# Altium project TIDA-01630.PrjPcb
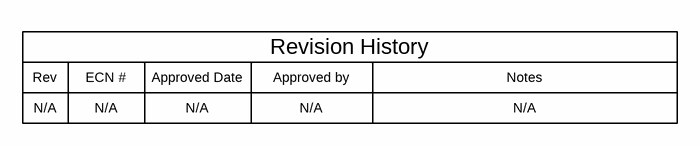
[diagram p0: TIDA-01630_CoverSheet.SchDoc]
TID: 01630; TechSupport: http://www.ti.com/support; SCH_Rev: E2; PRJ_Title: High EMC Immunity RS485 Interface  Reference Design for Tamagawa Encoders; PRJ_Number: TIDA-01630; PRJ_Engineer: Kristen Mogensen; PRJ_Customer: Internal Use Only; PCB_Rev: E2; PCB_Layout: Zoe Boele; CopyrightYear: 2017
5 sheets, 119 parts. Net scope: global (net labels, ports and power ports of the same name join across sheets).
Board file: TIDA-01630_PCB.PcbDoc
Sheets:
  TIDA-01630_CoverSheet.SchDoc
  TIDA-01630_EVM_Hardware.SchDoc
  TIDA-01630_Interface.SchDoc
  TIDA-01630_PowerSupply.SchDoc
  TIDA-01630_Transceivers.SchDoc

## Sheet TIDA-01630_CoverSheet.SchDoc
size 431 x 279 mm; Date: Not shown in title block; ApprovedBy: Not shown in title block; CheckedBy: Not shown in title block; Author: Not shown in title block; CompanyName: Not shown in title block; Engineer: Not shown in title block; Organization: Not shown in title block; Address1: Not shown in title block; Address2: Not shown in title block; Address3: Not shown in title block; Address4: Not shown in title block; DocumentNumber: 1; Revision: Use project parameter SCH_Rev; SheetNumber: 1; SheetTotal: 3; PageSetup: Record=PageOptions¦CenterHorizontal=True¦CenterVertical=True¦PrintScale=1.00¦XCorrection=1.00¦YCorrection=1.00¦PrintKind=0¦BorderSize=5000000¦LeftOffset=0¦BottomOffset=0¦Orientation=2¦PaperLength=1000¦PaperWidth=1000¦Scale=100¦PaperSource=15¦PrintQuality=600¦MediaType=1¦DitherType=10¦PaperKind=Letter¦PrintScaleMode=1

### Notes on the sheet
- Rev
- N/A
- ECN #
- Approved Date
- Approved by
- Revision History
- Notes

## Sheet TIDA-01630_EVM_Hardware.SchDoc
size 431 x 279 mm; Date: Not shown in title block; ApprovedBy: Not shown in title block; CheckedBy: Not shown in title block; Author: Not shown in title block; CompanyName: Not shown in title block; Engineer: Not shown in title block; Organization: Not shown in title block; Address1: Not shown in title block; Address2: Not shown in title block; Address3: Not shown in title block; Address4: Not shown in title block; DocumentNumber: 1; Revision: Use project parameter SCH_Rev; SheetNumber: 3; SheetTotal: 3; PageSetup: Record=PageOptions¦CenterHorizontal=True¦CenterVertical=True¦PrintScale=1.00¦XCorrection=1.00¦YCorrection=1.00¦PrintKind=0¦BorderSize=5000000¦LeftOffset=0¦BottomOffset=0¦Orientation=2¦PaperLength=1000¦PaperWidth=1000¦Scale=100¦PaperSource=15¦PrintQuality=600¦MediaType=1¦DitherType=10¦PaperKind=Letter¦PrintScaleMode=1
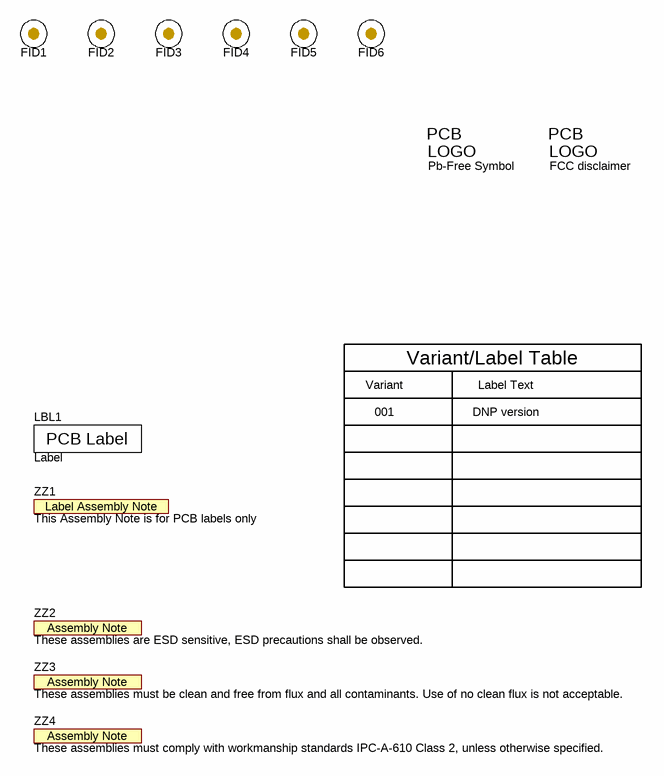
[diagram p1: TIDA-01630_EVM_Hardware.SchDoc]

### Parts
FID1  Fiducial  [Fiducial10-20]  (value not drawn)
FID2  Fiducial  [Fiducial10-20]  (value not drawn)
FID3  Fiducial  [Fiducial10-20]  (value not drawn)
FID4  Fiducial  [Fiducial10-20]  (value not drawn)
FID5  Fiducial  [Fiducial10-20]  (value not drawn)
FID6  Fiducial  [Fiducial10-20]  (value not drawn)
LBL1  Label  [Label_650x200]
Logo2  Pb-Free Symbol  [Pb-Free_Overlay_Small]  (no BOM)
Logo3  FCC disclaimer  [FCC_disclaimer]  (no BOM)
ZZ1  This Assembly Note is for PCB labels only  [AssemblyNoteLabel]  (no BOM)
ZZ2  These assemblies are ESD sensitive, ESD precautions shall be observed.  [AssemblyNote]  (no BOM)
ZZ3  These assemblies must be clean and free from flux and all contaminants. Use of no clean flux is not acceptable.  [AssemblyNote]  (no BOM)
ZZ4  These assemblies must comply with workmanship standards IPC-A-610 Class 2, unless otherwise specified.  [AssemblyNote]  (no BOM)

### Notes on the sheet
- Variant
- Variant/Label Table
- Label Text
- 001
- DNP version

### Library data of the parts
FID1-FID6 = CMP-0077181-1: Fiducial mark.  There is nothing to buy or mount.
LBL1 = CMP-0003625-1: Thermal Transfer Printable Labels, 0.650" W x 0.200" H - 10,000 per roll; Manufacturer: Brady; PartNumber: THT-14-423-10; Note: Size: 0.65" x 0.20 "
Logo2 = CMP-0074839-1: SymbolCreator: a0412235
Logo3 = CMP-0074847-1: FCC_disclaimer
ZZ1 = CMP-0003616-3
ZZ2 = CMP-0077236-1
ZZ3 = CMP-0077237-1
ZZ4 = CMP-0077238-1

## Sheet TIDA-01630_Interface.SchDoc
size 431 x 279 mm; Date: Not shown in title block; ApprovedBy: Not shown in title block; CheckedBy: Not shown in title block; Author: Not shown in title block; CompanyName: Not shown in title block; Engineer: Not shown in title block; Organization: Not shown in title block; Address1: Not shown in title block; Address2: Not shown in title block; Address3: Not shown in title block; Address4: Not shown in title block; DocumentNumber: 1; Revision: Use project parameter SCH_Rev; SheetNumber: 2; SheetTotal: 3; PageSetup: Record=PageOptions¦CenterHorizontal=True¦CenterVertical=True¦PrintScale=0.64¦XCorrection=1.00¦YCorrection=1.00¦PrintKind=0¦BorderSize=5000000¦LeftOffset=0¦BottomOffset=0¦Orientation=2¦PaperLength=1000¦PaperWidth=1000¦Scale=100¦PaperSource=15¦PrintQuality=600¦MediaType=1¦DitherType=10¦PrintScaleMode=1¦PaperKind=8 1/2x11¦PaperIndex=1
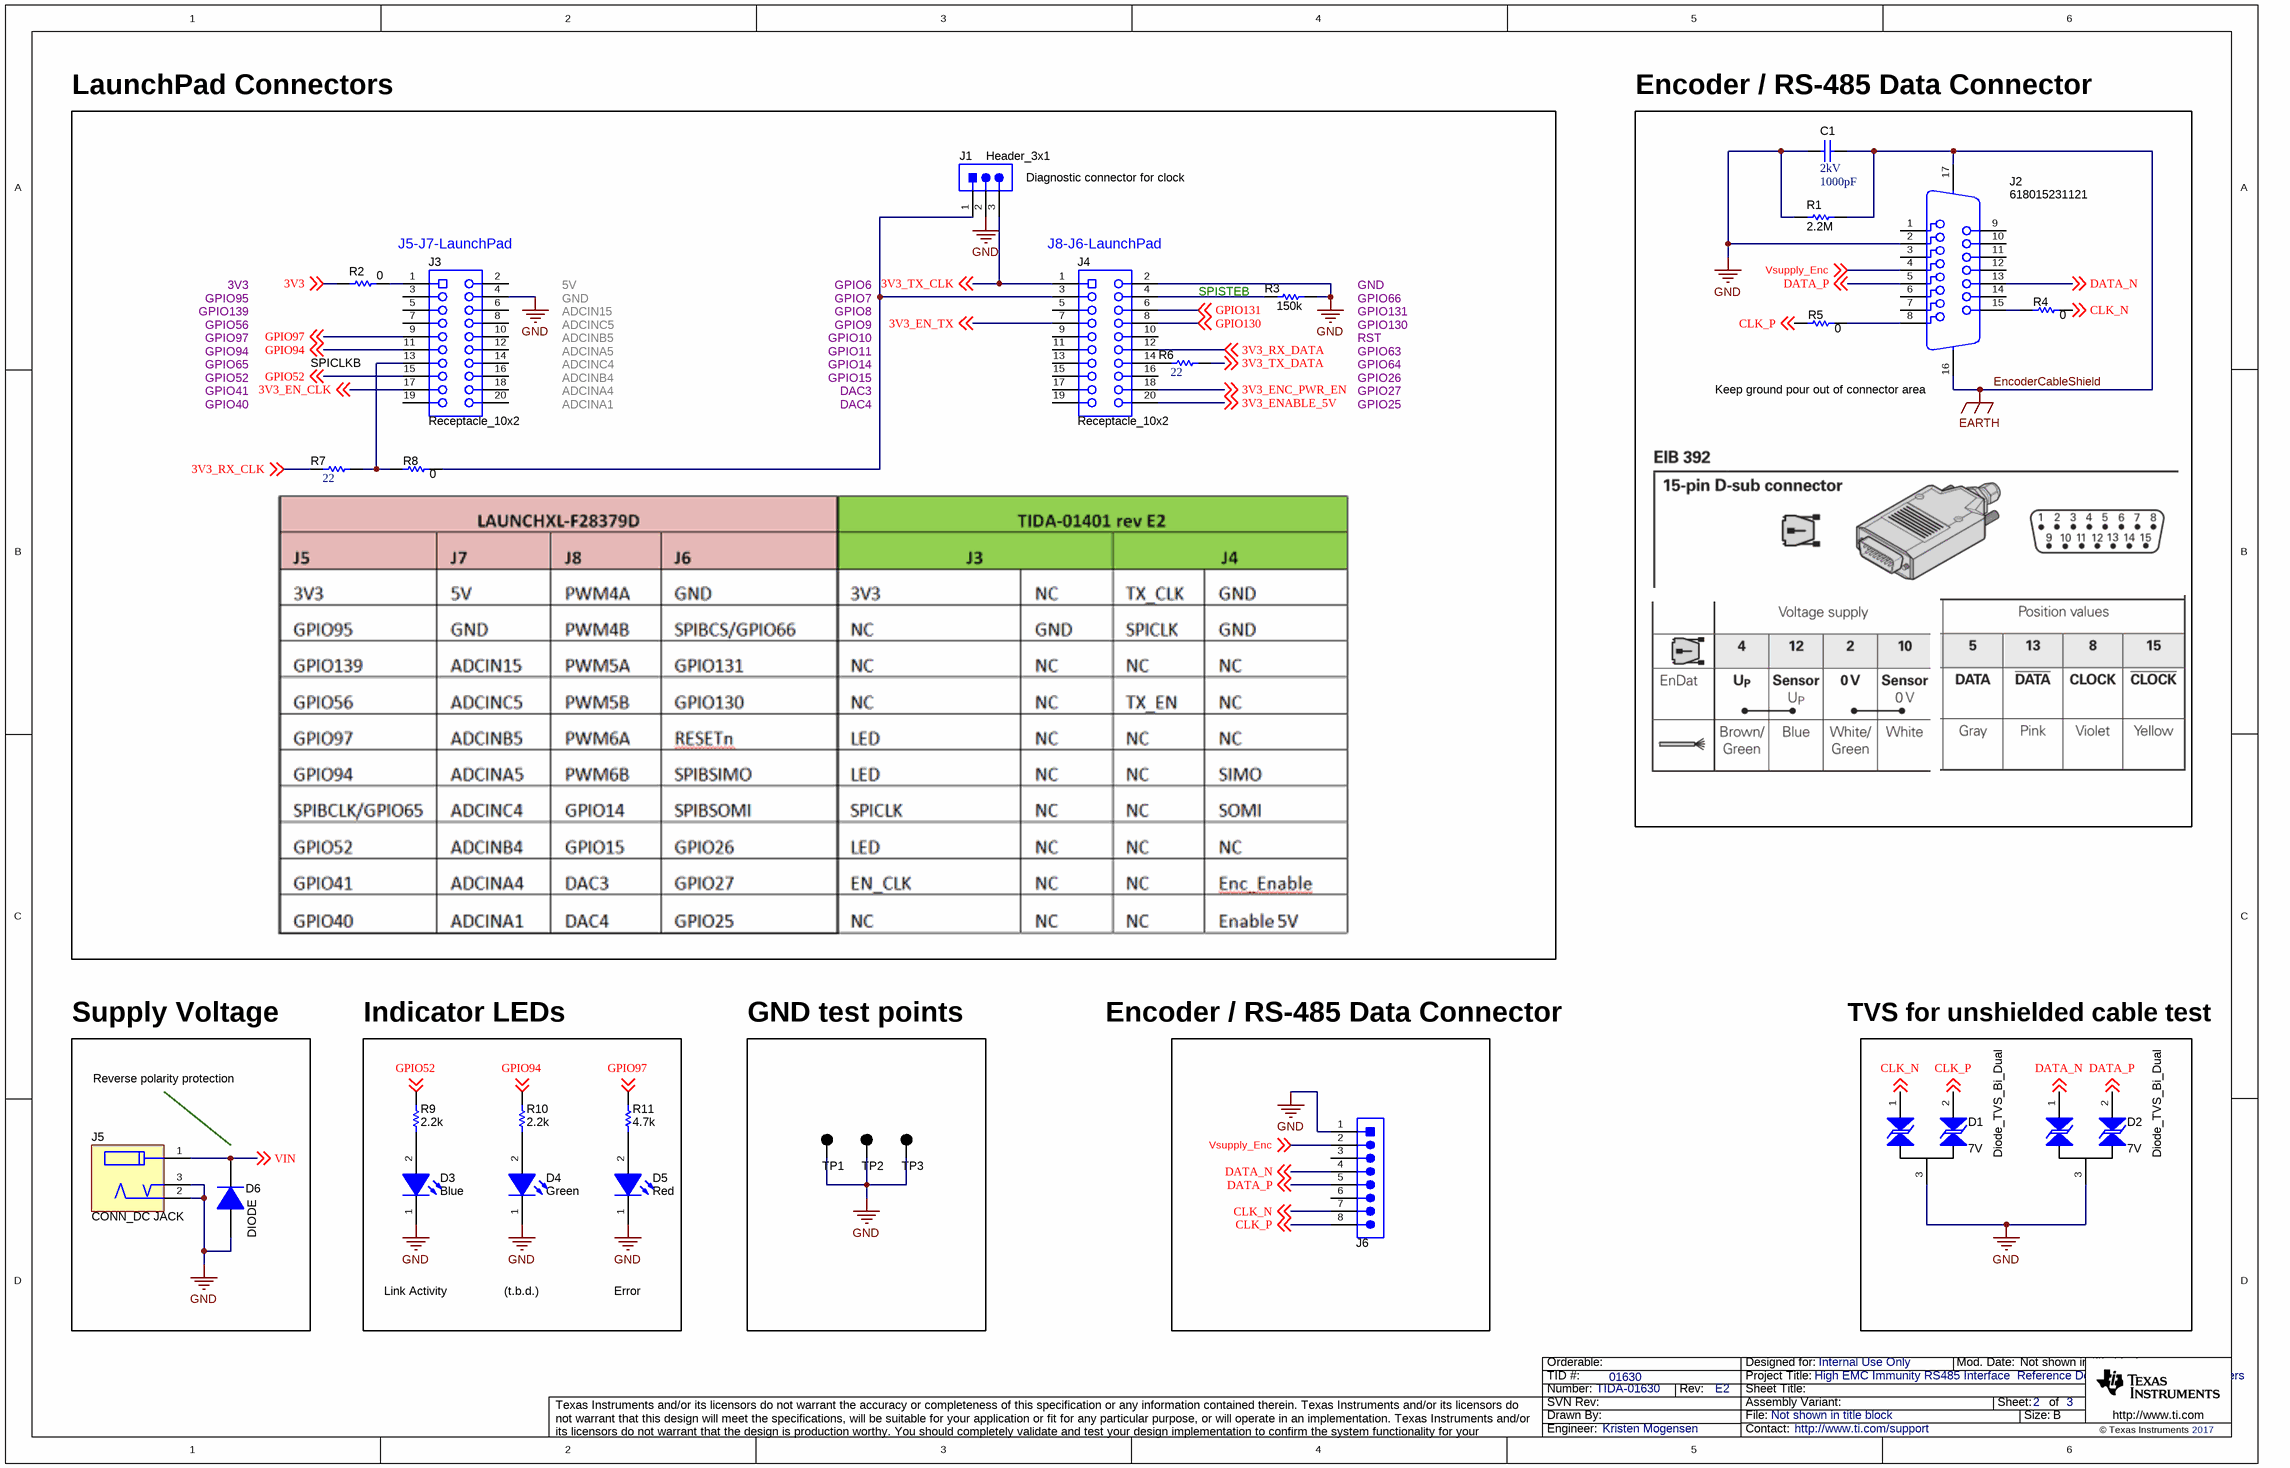
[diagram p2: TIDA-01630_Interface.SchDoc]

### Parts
C1  VDC_V: 2kV  ValueDisplayed: 1000pF  [1812_220]  (hidden comment: 1812GC102KAT1A)
D1  Diode_TVS_Bi_Dual  value 7V  [SOT-23]
D2  Diode_TVS_Bi_Dual  value 7V  [SOT-23]
D3  value Blue  [WL-SMCW_Blue]  (hidden comment: LED_A2_K1)
D4  value Green  [WL-SMCW_GREEN]  (hidden comment: LED_A2_K1)
D5  value Red  [WL-SMCW_RED]  (hidden comment: LED_A2_K1)
D6  DIODE  [PowerDI123]
J1  Header_3x1  [FCI_68001-403HLF]
J2  618015231121  [Wurth_618015231121]
J3  Receptacle_10x2  [CONN_SSW-110-23-F-D]
J4  Receptacle_10x2  [CONN_SSW-110-23-F-D]
J5  CONN_DC JACK  [Switchcraft_RASM722]
J6  Header_8x1  [SULLINS_PEC08SAAN]  (value not drawn)
R1  ValueDisplayed: 2.2M  [1206]  (hidden comment: Resistor)
R2  ValueDisplayed: 0  [0603]  (hidden comment: Resistor)
R3  ValueDisplayed: 150k  [0402S]  (hidden comment: Resistor)
R4  ValueDisplayed: 0  [0402S]  (hidden comment: Resistor)
R5  ValueDisplayed: 0  [0402S]  (hidden comment: Resistor)
R6  ValueDisplayed: 22  [0402S]  (hidden comment: CRCW040222R0JNED)
R7  ValueDisplayed: 22  [0402S]  (hidden comment: CRCW040222R0JNED)
R8  ValueDisplayed: 0  [0402S]  (hidden comment: Resistor)
R9  ValueDisplayed: 2.2k  [0402S]  (hidden comment: Resistor)
R10  ValueDisplayed: 2.2k  [0402S]  (hidden comment: Resistor)
R11  ValueDisplayed: 4.7k  [0402S]  (hidden comment: Resistor)
TP1  5001  [Keystone5001]  (value not drawn)
TP2  5001  [Keystone5001]  (value not drawn)
TP3  5001  [Keystone5001]  (value not drawn)

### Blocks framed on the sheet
Keep ground pour out of connector area: C1 J2 R1 R4 R5
Reverse polarity protection: D6 J5

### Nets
EncoderCableShield: C1.1 J2.16(MH1) J2.17(MH2) R1.2  [also labelled EARTH]
GND: C1.2 D1.3 D2.3 D3.1(K) D4.1(K) D5.1(K) D6.2(A) J1.2 J2.2 J3.4 J4.2 J5.2 J5.3 J6.1 R1.1 R3.2 TP1.1 TP2.1 TP3.1
3V3: R2.1 ; off-sheet 3V3
3V3_EN_CLK: J3.17 ; off-sheet 3V3_EN_CLK
3V3_EN_TX: J4.7 ; off-sheet 3V3_EN_TX
3V3_ENABLE_5V: J4.20 ; off-sheet 3V3_ENABLE_5V
3V3_ENC_PWR_EN: J4.18 ; off-sheet 3V3_ENC_PWR_EN
3V3_RX_CLK: R7.1 ; off-sheet 3V3_RX_CLK
3V3_RX_DATA: J4.12 ; off-sheet 3V3_RX_DATA
3V3_TX_CLK: J1.3 J4.1 ; off-sheet 3V3_TX_CLK
3V3_TX_DATA: R6.2 ; off-sheet 3V3_TX_DATA
CLK_N: D1.1 J6.7 R4.2 ; off-sheet CLK_N
CLK_P: D1.2 J6.8 R5.1 ; off-sheet CLK_P
DATA_N: D2.1 J2.13 J6.4 ; off-sheet DATA_N
DATA_P: D2.2 J2.5 J6.5 ; off-sheet DATA_P
GPIO52: J3.15 R9.2 ; off-sheet GPIO52
GPIO94: J3.11 R10.2 ; off-sheet GPIO94
GPIO97: J3.9 R11.2 ; off-sheet GPIO97
GPIO130: J4.8 ; off-sheet GPIO130
GPIO131: J4.6 ; off-sheet GPIO131
VIN: D6.1(K) J5.1 ; off-sheet VIN
Vsupply_Enc: J2.4 J6.2 ; off-sheet Vsupply_Enc
NetD3_2: D3.2(A) R9.1
NetD4_2: D4.2(A) R10.1
NetD5_2: D5.2(A) R11.1
NetJ1_1: J1.1 J4.3 R8.2
NetJ2_8: J2.8 R5.2
NetJ2_15: J2.15 R4.1
NetJ3_1: J3.1 R2.2
NetJ3_13: J3.13 R7.2 R8.1
NetJ4_4: J4.4 R3.1
NetJ4_14: J4.14 R6.1

Not connected (* = marked no-connect by the designer): J2 1 3 6 7 9 10 11 12 14; J3 2 3 5 6 7 8 10 12 14 16 18 19 20; J4 5 9 10 11 13 15 16 17 19; J6 3 6

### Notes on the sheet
- LaunchPad Connectors
- (near C1) Encoder / RS-485 Data Connector
- (near J1) Diagnostic connector for clock
- J5-J7-LaunchPad
- (near J4) J8-J6-LaunchPad
- (near R3) SPISTEB
- SPICLKB
- 3V3
  GPIO95
  GPIO139
  GPIO56
  GPIO97
  GPIO94
  GPIO65
  GPIO52
  GPIO41
  GPIO40
- 5V
  GND
  ADCIN15
  ADCINC5
  ADCINB5
  ADCINA5
  ADCINC4
  ADCINB4
  ADCINA4
  ADCINA1
- GPIO6
  GPIO7
  GPIO8
  GPIO9
  GPIO10
  GPIO11
  GPIO14
  GPIO15
  DAC3
  DAC4
- GND
  GPIO66
  GPIO131
  GPIO130
  RST
  GPIO63
  GPIO64
  GPIO26
  GPIO27
  GPIO25
- Supply Voltage
- Indicator LEDs
- GND test points
- Encoder / RS-485 Data Connector
- TVS for unshielded cable test
- Link Activity
- (t.b.d.)
- Error

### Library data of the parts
C1 = CMP-0064918-2: CAP, CERM, 1000 pF, 2000 V,+/- 10%, X7R, 1812; Manufacturer: AVX; TaMin_C: -55°C; Polarized: N; SizeAreaWB_mm2: 23.1; Value1: Unknown; U/M: EA; Value: 1000pF; TaMax_C: 125°C; SizeZ_mm: 2.2; SizeX_mm: 4.5; SizeY_mm: 3.2; Cap_Case: 1812; Value2: 2000V; SizeArea_mm2: 14.4; CompType: Capacitor; Cap_F: 1nF; AEC Category: Q200
D1 D2 = CMP-0005928-1: Diode, TVS, Bi, 7 V, SOT-23; PartNumber: CDSOT23-SM712; Manufacturer: Bourns; U/M: EA; Value1: W; SizeAreaWB_mm2: 14; SizeArea_mm2: 7.5; SizeX_mm: 2.5; SizeY_mm: 3; SizeZ_mm: 1.1; AEC Category: Q101
D3 = CMP-0002946-2: LED, Blue, SMD; Manufacturer: Wurth Elektronik; PartNumber: 150060BS75000; Type: InGaN; Vf_V: 3.2V; Io_A: 30mA; Vr_V: 5V; Tjmax_C: 85°C; Power_TotalModule: 105mW; Value1: 0.105W; Angle: 140; U/M: EA
D4 = CMP-0002905-1: LED, Green, SMD; Manufacturer: Wurth Elektronik; PartNumber: 150060GS75000; Type: InGaN; Vf_V: 3.2V; Io_A: 20mA; Tjmax_C: 85°C; Value1: W; Angle: 140; U/M: EA
D5 = CMP-0002947-2: LED, Red, SMD; Manufacturer: Wurth Elektronik; PartNumber: 150060RS75000; Type: AlInGaP; Vf_V: 2V; Io_A: 30mA; Vr_V: 5V; Tjmax_C: 85°C; Power_TotalModule: 72mW; Value1: 0.072W; Angle: 140; U/M: EA
D6 = CMP-0029284-1: Diode, Super Barrier Rectifier, 40 V, 3 A, AEC-Q101, PowerDI123; PartNumber: SBRT3U40P1-7; Manufacturer: Diodes Inc.; U/M: EA; Vf_V: 4.9dV; Value: 40V; Value1: 3A; Value2: 0.49V; TJmax_C: 150°C; RJC_CperW: 19; SizeAreaWB_mm2: 13.066; SizeArea_mm2: 6.586; SizeX_mm: 3.7; SizeY_mm: 1.78; SizeZ_mm: 0.98; AEC Category: Q101; AEC Qualified: Y; Green_Lifecycle: Not Set; Green_REACh: Incomplete
J1 = CMP-0065026-1: Header, 2.54mm, 3x1, Tin, TH; PartNumber: 68001-403HLF; Manufacturer: FCI; Pitch_mm: 2.54; Gender: Male; Shrouded: N; Row_Count: 1; Current_A: 3A; Voltage_V: 1.5kV; Cert_CSA: Y; CNHeader: True; CT: False
J2 = CMP-0077259-1: Receptacle, D-Sub, 15 Position, R/A, TH; Manufacturer: Wurth Elektronik; Pitch_mm: 2.77; Gender: Female; Cert_UL: Y; Current_A: 3A; Voltage_V: 125V; ContactFinish: Gold; RowSpacing_mm: 2.84; Row_Count: 2
J3 J4 = CMP-0075442-1: Connector, Receptacle, 100mil, 10x2, Gold plated, TH; PartNumber: SSW-110-23-F-D; Manufacturer: Samtec; CompType: Socket Strip; CNHeader: False; CT: True; Green_Lifecycle: Active; Green_REACh: Passed
J5 = CMP-0075046-1: Power Jack, 2mm, R/A, SMD; PartNumber: RASM722X; Manufacturer: Switchcraft; CNHeader: False
J6 = CMP-0054563-1: Header, 100mil, 8x1, Tin, TH; PartNumber: PEC08SAAN; Manufacturer: Sullins Connector Solutions; Pitch_mm: 2.54; Gender: Male; Shrouded: N; Row_Count: 1; Current_A: 3A; Voltage_V: 1.8kV; Cert_UL: Y; CNHeader: TRUE; CT: FALSE; Green_Lifecycle: Not Set; Green_REACh: Incomplete
R1 = CMP-0018645-2: RES, 2.2 M, 5%, 0.25 W, 1206; PartNumber: CRCW12062M20JNEA; Manufacturer: Vishay-Dale; Value: 2.2Meg; Value_Code: 2M20; Power_W: 250mW; Value2: 0.25W; VDC_V: 200V; TempCo: 200 ppm/C; SizeArea_mm2: 5.12; SizeX_mm: 3.2; SizeY_mm: 1.6; SizeZ_mm: 1.35; EIA_Code: E24; U/M: EA; AEC Category: Q200
R2 = CMP-0025697-4: RES, 0, 5%, 0.1 W, AEC-Q200 Grade 0, 0603; PartNumber: CRCW06030000Z0EA; Manufacturer: Vishay-Dale; Value: 0; Value_Code: 0000; Power_W: 100mW; Value2: 0.1W; VDC_V: 75V; TempCo: 200 ppm/C; SizeArea_mm2: 1.28; SizeX_mm: 1.6; SizeY_mm: 0.8; SizeZ_mm: 1; EIA_Code: E24; AEC Category: Q200; AEC Qualified: Y
R3 = CMP-0026840-2: RES, 150 k, 5%, 0.063 W, AEC-Q200 Grade 0, 0402; PartNumber: CRCW0402150KJNED; Manufacturer: Vishay-Dale; Value: 150k; Power_W: 63mW; Value2: 0.063W; VDC_V: 50V; TempCo: 200 ppm/C; SizeArea_mm2: 0.5; SizeX_mm: 1; SizeZ_mm: 0.6; EIA_Code: E24; AEC Category: Q200; AEC Qualified: Y; AEC Grade: 0
R4 R5 R8 = CMP-0026822-3: RES, 0, 5%, 0.063 W, AEC-Q200 Grade 0, 0402; PartNumber: CRCW04020000Z0ED; Manufacturer: Vishay-Dale; Value: 0; Value_Code: 0000; Power_W: 63mW; Value2: 0.063W; VDC_V: 50V; TempCo: 200 ppm/C; SizeArea_mm2: 0.5; SizeX_mm: 1; SizeZ_mm: 0.6; EIA_Code: E24; AEC Category: Q200; AEC Qualified: Y
R6 R7 = CMP-0026880-2: RES, 22, 5%, 0.063 W, 0402; Manufacturer: Vishay-Dale; Power_W: 63mW; TempCo: 200 ppm/C; Value_Code: 22R0; U/M: EA; Value: 22; EIA_Code: E24; SizeX_mm: 1; SizeY_mm: 0.5; SizeZ_mm: 0.6; Value2: 0.063W; CompType: Resistor; VDC_V: 50V; AEC Category: Q200
R9 R10 = CMP-0026890-5: RES, 2.2 k, 5%, 0.063 W, AEC-Q200 Grade 0, 0402; PartNumber: CRCW04022K20JNED; Manufacturer: Vishay-Dale; Value: 2.2k; Value_Code: 2k20; Power_W: 63mW; Value2: 0.063W; VDC_V: 50V; TempCo: 200 ppm/C; SizeArea_mm2: 0.5; SizeX_mm: 1; SizeZ_mm: 0.6; EIA_Code: E24; AEC Category: Q200; AEC Qualified: Y; AEC Grade: 0
R11 = CMP-0026938-5: RES, 4.7 k, 5%, 0.063 W, AEC-Q200 Grade 0, 0402; PartNumber: CRCW04024K70JNED; Manufacturer: Vishay-Dale; Value: 4.7k; Value_Code: 4k70; Power_W: 63mW; Value2: 0.063W; VDC_V: 50V; TempCo: 200 ppm/C; SizeArea_mm2: 0.5; SizeX_mm: 1; SizeZ_mm: 0.6; EIA_Code: E24; AEC Category: Q200; AEC Qualified: Y; AEC Grade: 0
TP1-TP3 = CMP-0055138-1: Test Point, Miniature, Black, TH; Manufacturer: Keystone; ContactFinish: Silver; CNHeader: FALSE; CT: TRUE; Green_Lifecycle: Active; Green_REACh: Passed

## Sheet TIDA-01630_PowerSupply.SchDoc
size 431 x 279 mm; Date: Not shown in title block; ApprovedBy: Not shown in title block; CheckedBy: Not shown in title block; Author: Not shown in title block; CompanyName: Not shown in title block; Engineer: Not shown in title block; Organization: Not shown in title block; Address1: Not shown in title block; Address2: Not shown in title block; Address3: Not shown in title block; Address4: Not shown in title block; DocumentNumber: 1; Revision: Use project parameter SCH_Rev; SheetNumber: 2; SheetTotal: 3; PageSetup: Record=PageOptions¦CenterHorizontal=True¦CenterVertical=True¦PrintScale=1.00¦XCorrection=1.00¦YCorrection=1.00¦PrintKind=0¦BorderSize=5000000¦LeftOffset=0¦BottomOffset=0¦Orientation=2¦PaperLength=1000¦PaperWidth=1000¦Scale=100¦PaperSource=15¦PrintQuality=600¦MediaType=1¦DitherType=10¦PaperKind=Letter¦PrintScaleMode=1
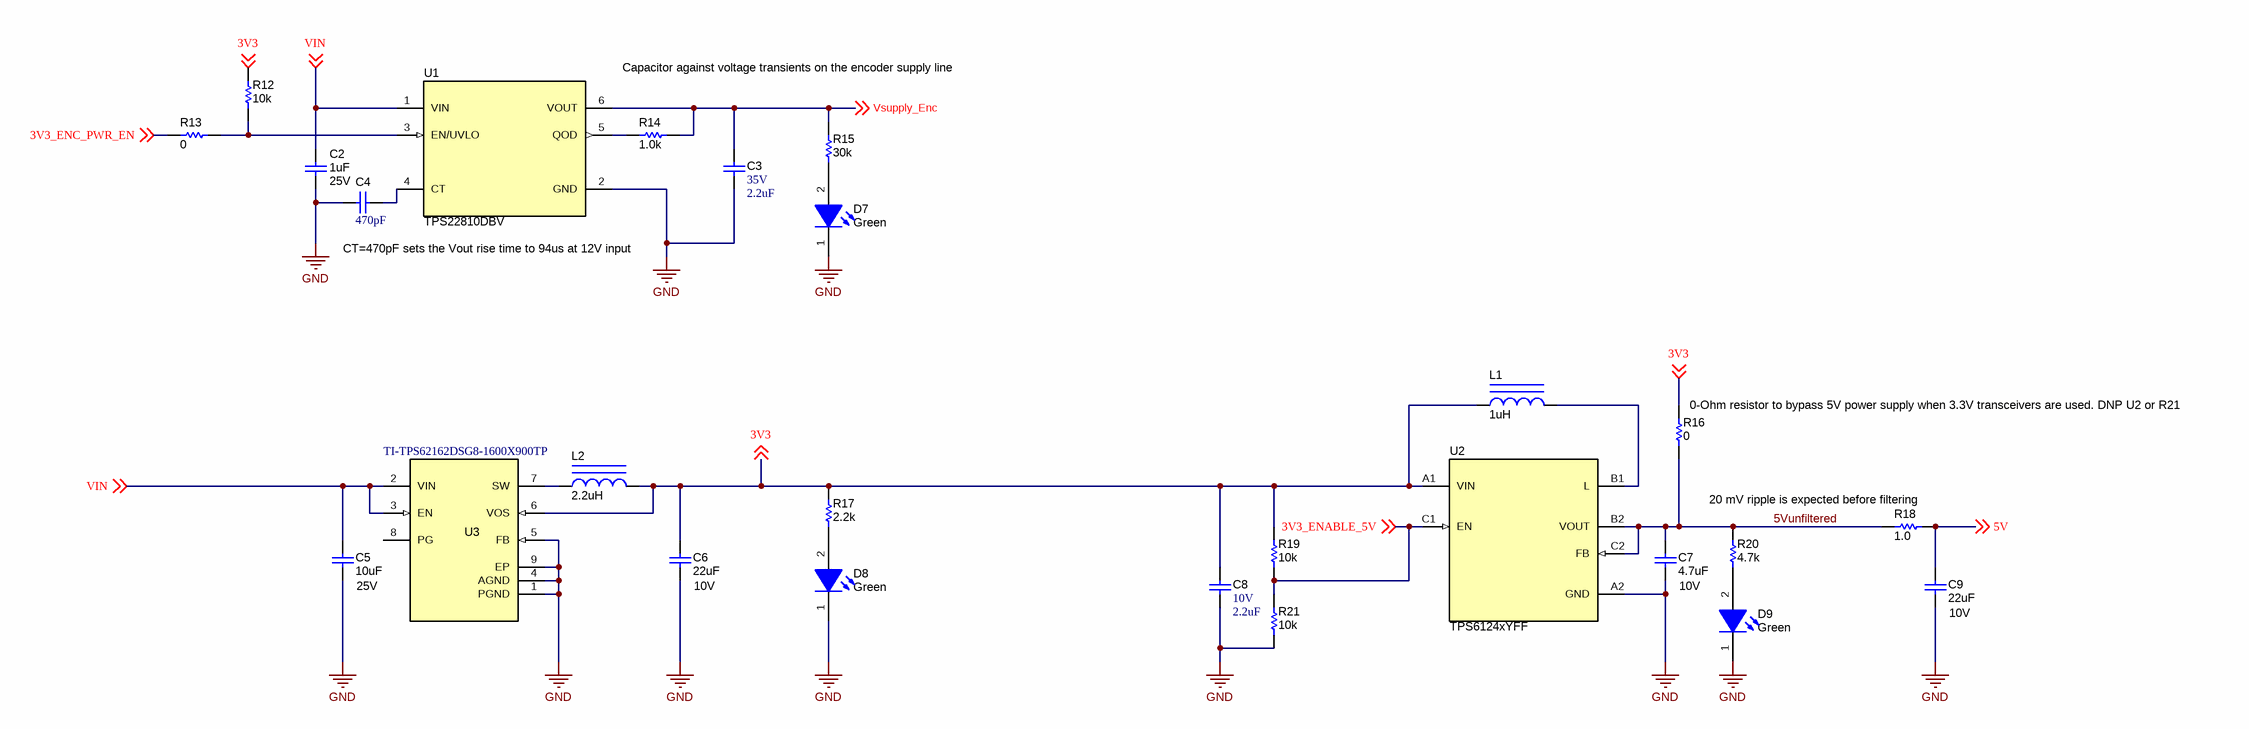
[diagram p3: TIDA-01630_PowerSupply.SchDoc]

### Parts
C2  ValueDisplayed: 1uF  Value2: 25V  [0603S]  (hidden comment: Capacitor)
C3  VDC_V: 35V  ValueDisplayed: 2.2uF  [0402_070]  (hidden comment: GRM155R6YA225ME11D)
C4  ValueDisplayed: 470pF  [0402S]  (hidden comment: GRM155R71H471KA01D)
C5  ValueDisplayed: 10uF  Value2: 25V  [0603S]  (hidden comment: Capacitor)
C6  ValueDisplayed: 22uF  Value2: 10V  [0603S]  (hidden comment: Capacitor)
C7  ValueDisplayed: 4.7uF  Value2: 10V  [0402_065S]  (hidden comment: Capacitor)
C8  VDC_V: 10V  ValueDisplayed: 2.2uF  [0402S]  (hidden comment: 885012105013)
C9  ValueDisplayed: 22uF  Value2: 10V  [0603S]  (hidden comment: Capacitor)
D7  value Green  [WL-SMCW_GREEN]  (hidden comment: LED_A2_K1)
D8  value Green  [WL-SMCW_GREEN]  (hidden comment: LED_A2_K1)
D9  value Green  [WL-SMCW_GREEN]  (hidden comment: LED_A2_K1)
L1  ValueDisplayed: 1uH  [WE-PMI_0805LR]  (hidden comment: Inductor_Iron)
L2  ValueDisplayed: 2.2uH  [XFL3012]  (hidden comment: Inductor_Iron)
R12  ValueDisplayed: 10k  [0402]  (hidden comment: Resistor)
R13  ValueDisplayed: 0  [0402]  (hidden comment: Resistor)
R14  ValueDisplayed: 1.0k  [0603S]  (hidden comment: Resistor)
R15  ValueDisplayed: 30k  [0402S]  (hidden comment: Resistor)
R16  ValueDisplayed: 0  [0402]  (hidden comment: Resistor)
R17  ValueDisplayed: 2.2k  [0402S]  (hidden comment: Resistor)
R18  ValueDisplayed: 1.0  [0603S]  (hidden comment: Resistor)
R19  ValueDisplayed: 10k  [0402]  (hidden comment: Resistor)
R20  ValueDisplayed: 4.7k  [0402S]  (hidden comment: Resistor)
R21  ValueDisplayed: 10k  [0402]  (hidden comment: Resistor)
U1  TPS22810DBV  [DBV0006A_N]
U2  TPS6124xYFF  [YFF0006AEAE]
U3  TI-TPS62162DSG8-1600X900TP  [DSG0008A]

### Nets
GND: C2.2 C3.2 C4.1 C5.2 C6.2 C7.2 C8.2 C9.2 D7.1(K) D8.1(K) D9.1(K) R21.1 U1.2(GND) U2.A2(GND) U3.1(PGND) U3.4(AGND) U3.5(FB) U3.9(EP)
3V3: C6.1 C8.1 L1.1 L2.2 R12.2 R16.2 R17.2 R19.2 U2.A1(VIN) U3.6(VOS) ; off-sheet 3V3
3V3_ENABLE_5V: R19.1 R21.2 U2.C1(EN) ; off-sheet 3V3_ENABLE_5V
3V3_ENC_PWR_EN: R13.1 ; off-sheet 3V3_ENC_PWR_EN
5V: C9.1 R18.2 ; off-sheet 5V
5Vunfiltered: C7.1 R16.1 R18.1 R20.2 U2.B2(VOUT) U2.C2(FB)
VIN: C2.1 C5.1 U1.1(VIN) U3.2(VIN) U3.3(EN) ; off-sheet VIN
Vsupply_Enc: C3.1 R14.2 R15.1 U1.6(VOUT) ; off-sheet Vsupply_Enc
NetC4_2: C4.2 U1.4(CT)
NetD7_2: D7.2(A) R15.2
NetD8_2: D8.2(A) R17.1
NetD9_2: D9.2(A) R20.1
NetL1_2: L1.2 U2.B1(L)
NetL2_1: L2.1 U3.7(SW)
NetR12_1: R12.1 R13.2 U1.3(EN/UVLO)
NetR14_1: R14.1 U1.5(QOD)

Not connected (* = marked no-connect by the designer): U3 8(PG)

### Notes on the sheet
- (near U1) Capacitor against voltage transients on the encoder supply line
- CT=470pF sets the Vout rise time to 94us at 12V input
- (near R16) 0-Ohm resistor to bypass 5V power supply when 3.3V transceivers are used. DNP U2 or R21
- 20 mV ripple is expected before filtering

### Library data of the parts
C2 = CMP-0006833-4: CAP, CERM, 1 uF, 25 V, +/- 10%, X7R, 0603; PartNumber: 885012206076; Manufacturer: Wurth Elektronik; Polarized: N; Value: 1uF; U/M: EA; Cap_F: 1µF; Value1: Unknown; TaMin_C: -55°C; TaMax_C: 125°C; Cap_Case: 0603; SizeArea_mm2: 1.28; SizeAreaWB_mm2: 4.68; SizeX_mm: 1.6; SizeY_mm: 0.8; SizeZ_mm: 1; AEC Category: Q200
C3 = CMP-0006621-2: CAP, CERM, 2.2 uF, 35 V, +/- 20%, X5R, 0402; Manufacturer: MuRata; TaMin_C: -55°C; Polarized: N; SizeAreaWB_mm2: 3; Value1: Unknown; U/M: EA; Value: 2.2uF; TaMax_C: 85°C; SizeZ_mm: 0.7; SizeX_mm: 1; SizeY_mm: 0.5; Cap_Case: 0402; CompType: Capacitor; Cap_F: 2.2µF; AEC Category: Q200
C4 = CMP-0006691-2: CAP, CERM, 470 pF, 50 V, +/- 10%, X7R, 0402; Manufacturer: MuRata; TaMin_C: -55°C; Polarized: N; SizeAreaWB_mm2: 3; Value1: Unknown; U/M: EA; Value: 470pF; TaMax_C: 125°C; SizeZ_mm: 0.6; SizeX_mm: 1; SizeY_mm: 0.5; Cap_Case: 0402; Value2: 50V; CompType: Capacitor; AEC Category: Q200
C5 = CMP-0007007-5: CAP, CERM, 10 uF, 25 V, +/- 20%, X5R, 0603; PartNumber: C1608X5R1E106M080AC; Manufacturer: TDK; Polarized: N; Value: 10uF; U/M: EA; Cap_F: 10µF; ESR_ohm: 4.639m; Value1: 0.004639 ohm; IRMS_A: 2.41407A; TaMin_C: -55°C; TaMax_C: 85°C; Cap_Case: 0603; SizeArea_mm2: 1.28; SizeAreaWB_mm2: 4.68; SizeX_mm: 1.6; SizeY_mm: 0.8; SizeZ_mm: 1; AEC Category: Q200
C6 C9 = CMP-0007158-5: CAP, CERM, 22 uF, 10 V, +/- 20%, X5R, 0603; PartNumber: GRM187R61A226ME15D; Manufacturer: MuRata; Polarized: N; Value: 22uF; U/M: EA; Cap_F: 22µF; Value1: Unknown; TaMin_C: -55°C; TaMax_C: 85°C; Cap_Case: 0603; SizeArea_mm2: 1.28; SizeAreaWB_mm2: 4.68; SizeX_mm: 1.6; SizeY_mm: 0.8; SizeZ_mm: 1; AEC Category: Q200
C7 = CMP-0006268-2: CAP, CERM, 4.7 uF, 10 V, +/- 10%, X5R, 0402; PartNumber: C1005X5R1A475K050BC; Manufacturer: TDK; Polarized: N; Value: 4.7uF; U/M: EA; Cap_F: 4.7µF; ESR_ohm: 3.417m; Value1: 0.003417 ohm; IRMS_A: 2.7063A; TaMin_C: -55°C; TaMax_C: 85°C; Cap_Case: 0402_065; SizeArea_mm2: 0.5; SizeAreaWB_mm2: 3; SizeX_mm: 1; SizeZ_mm: 0.65; AEC Category: Q200
C8 = CMP-0006222-2: CAP, CERM, 2.2 uF, 10 V, +/- 20%, X5R, 0402; Manufacturer: Wurth Elektronik; TaMin_C: -55°C; Polarized: N; SizeAreaWB_mm2: 3; Value1: Unknown; U/M: EA; Value: 2.2uF; TaMax_C: 85°C; SizeZ_mm: 0.6; SizeX_mm: 1; SizeY_mm: 0.5; Cap_Case: 0402; CompType: Capacitor; Cap_F: 2.2µF; AEC Category: Q200
D7-D9 = CMP-0002905-1: as D4 on sheet TIDA-01630_Interface
L1 = CMP-0064319-1: Inductor, Shielded Drum Core, Metal Composite, 1 uH, 0.7 A, 0.1 ohm, SMD; PartNumber: 74479775210; Manufacturer: Wurth Elektronik; Value: 1uH; Ind_H: 1µH; Imax_A: 7dA; Irms: 1.1A @ 40C rise; Isat: 0.7A @ 30% inductance drop; DCR_ohm: 1d; Value1: 0.1 ohm; Value2: 0.7A; SizeAreaWB_mm2: 6.6; SizeArea_mm2: 2.4; SizeX_mm: 2; SizeY_mm: 1.2; SizeZ_mm: 1; AEC Category: Q200; Green_Lifecycle: Active; Green_REACh: Passed
L2 = CMP-0061137-1: Inductor, Shielded, Composite, 2.2 uH, 1.6 A, 0.08 ohm, SMD; PartNumber: XFL3012-222MEB; Manufacturer: Coilcraft; Value: 2.2uH; Ind_H: 2.2µH; Imax_A: 1.6A; Irms: 1.9A @ 40C rise; Isat: 1.6A @ 30% inductance drop; DCR_ohm: 0.08; SizeAreaWB_mm2: 16; SizeArea_mm2: 9; SizeX_mm: 3; SizeZ_mm: 1.2; AEC Category: Q200; Green_Lifecycle: Not Set; Green_REACh: Incomplete
R12 R19 R21 = CMP-0026825-5: RES, 10 k, 5%, 0.063 W, AEC-Q200 Grade 0, 0402; PartNumber: CRCW040210K0JNED; Manufacturer: Vishay-Dale; Value: 10k; Value_Code: 10k0; Power_W: 63mW; Value2: 0.063W; VDC_V: 50V; TempCo: 200 ppm/C; SizeArea_mm2: 0.5; SizeX_mm: 1; SizeZ_mm: 0.6; EIA_Code: E24; AEC Category: Q200; AEC Qualified: Y; AEC Grade: 0
R13 R16 = CMP-0026822-3: as R4 on sheet TIDA-01630_Interface
R14 = CMP-0025729-4: RES, 1.0 k, 5%, 0.1 W, AEC-Q200 Grade 0, 0603; PartNumber: CRCW06031K00JNEA; Manufacturer: Vishay-Dale; Value: 1.0k; Res_ohm: 1k; Value_Code: 1k00; Power_W: 100mW; Value2: 0.1W; VDC_V: 75V; TempCo: 200 ppm/C; SizeArea_mm2: 1.28; SizeX_mm: 1.6; SizeY_mm: 0.8; SizeZ_mm: 1; EIA_Code: E24; AEC Category: Q200; AEC Qualified: Y; AEC Grade: 0
R15 = CMP-0026903-3: RES, 30 k, 5%, 0.063 W, AEC-Q200 Grade 0, 0402; PartNumber: CRCW040230K0JNED; Manufacturer: Vishay-Dale; Value: 30k; Value_Code: 30k0; Power_W: 63mW; Value2: 0.063W; VDC_V: 50V; TempCo: 200 ppm/C; SizeArea_mm2: 0.5; SizeX_mm: 1; SizeZ_mm: 0.6; EIA_Code: E24; AEC Category: Q200; AEC Qualified: Y; AEC Grade: 0
R17 = CMP-0026890-5: as R9 on sheet TIDA-01630_Interface
R18 = CMP-0025743-4: RES, 1.0, 5%, 0.1 W, AEC-Q200 Grade 0, 0603; PartNumber: CRCW06031R00JNEA; Manufacturer: Vishay-Dale; Value: 1.0; Res_ohm: 1; Value_Code: 1R00; Power_W: 100mW; Value2: 0.1W; VDC_V: 75V; TempCo: 200 ppm/C; SizeArea_mm2: 1.28; SizeX_mm: 1.6; SizeY_mm: 0.8; EIA_Code: E24; AEC Category: Q200; AEC Qualified: Y; AEC Grade: 0
R20 = CMP-0026938-5: as R11 on sheet TIDA-01630_Interface
U1 = CMP-0073661-1: 2.7-18-V, 2-A, 79-mΩ On-Resistance Load Switch with Thermal Protection, DBV0006A (SOT-23-6); PartNumber: TPS22810DBVR; Alternate PartNumber: TPS22810DBVT; Manufacturer: Texas Instruments; SizeArea_mm2: 8.12; SizeAreaWB_mm2: 14.82; SizeX_mm: 2.8; SizeY_mm: 2.9; SizeZ_mm: 1.45; CompType: IC; U/M: EA; Green_Lifecycle: Active; Green_REACh: Passed
U2 = CMP-0067211-1: 5V, 400mA, 4MHz Step-Up DC/DC Converter, YFF0006AEAE (DSBGA-6); PartNumber: TPS61240YFFR; Alternate PartNumber: TPS61240YFFT; Manufacturer: Texas Instruments; SizeArea_mm2: 1.076848; SizeAreaWB_mm2: 4.190848; SizeX_mm: 0.856; SizeY_mm: 1.258; SizeZ_mm: 0.625; CompType: IC; U/M: EA
U3 = CMP-0037789-2: Buck Step Down Regulator with 3 to 17 V Input and 3.3 V Output, -40 to 85 degC, 8-Pin WSON (DSG), Green (RoHS & no Sb/Br); PartNumber: TPS62162DSGR; Manufacturer: Texas Instruments; Duty Cycle(Max)(%): 100; Iout(Max)(A): 1; Iq(Typ)(mA): 0.017; Preset Vout(V): 3.3; Rating: Catalog; SubFamily: Step-Down Regulator; Switch Current Limit(Typ)(A): 1.8; Synchronous Rectification: TRUE; Vin(Max)(V): 17; Vin(Min)(V): 3

## Sheet TIDA-01630_Transceivers.SchDoc
size 431 x 279 mm; Date: Not shown in title block; ApprovedBy: Not shown in title block; CheckedBy: Not shown in title block; Author: Not shown in title block; CompanyName: Not shown in title block; Engineer: Not shown in title block; Organization: Not shown in title block; Address1: Not shown in title block; Address2: Not shown in title block; Address3: Not shown in title block; Address4: Not shown in title block; DocumentNumber: 1; Revision: Use project parameter SCH_Rev; SheetNumber: 2; SheetTotal: 3; PageSetup: Record=PageOptions¦CenterHorizontal=True¦CenterVertical=True¦PrintScale=0.91¦XCorrection=1.00¦YCorrection=1.00¦PrintKind=0¦BorderSize=5000000¦LeftOffset=0¦BottomOffset=0¦Orientation=2¦PaperLength=1000¦PaperWidth=1000¦Scale=100¦PaperSource=15¦PrintQuality=-3¦MediaType=1¦DitherType=10¦PrintScaleMode=1¦PaperKind=A4¦PaperIndex=9
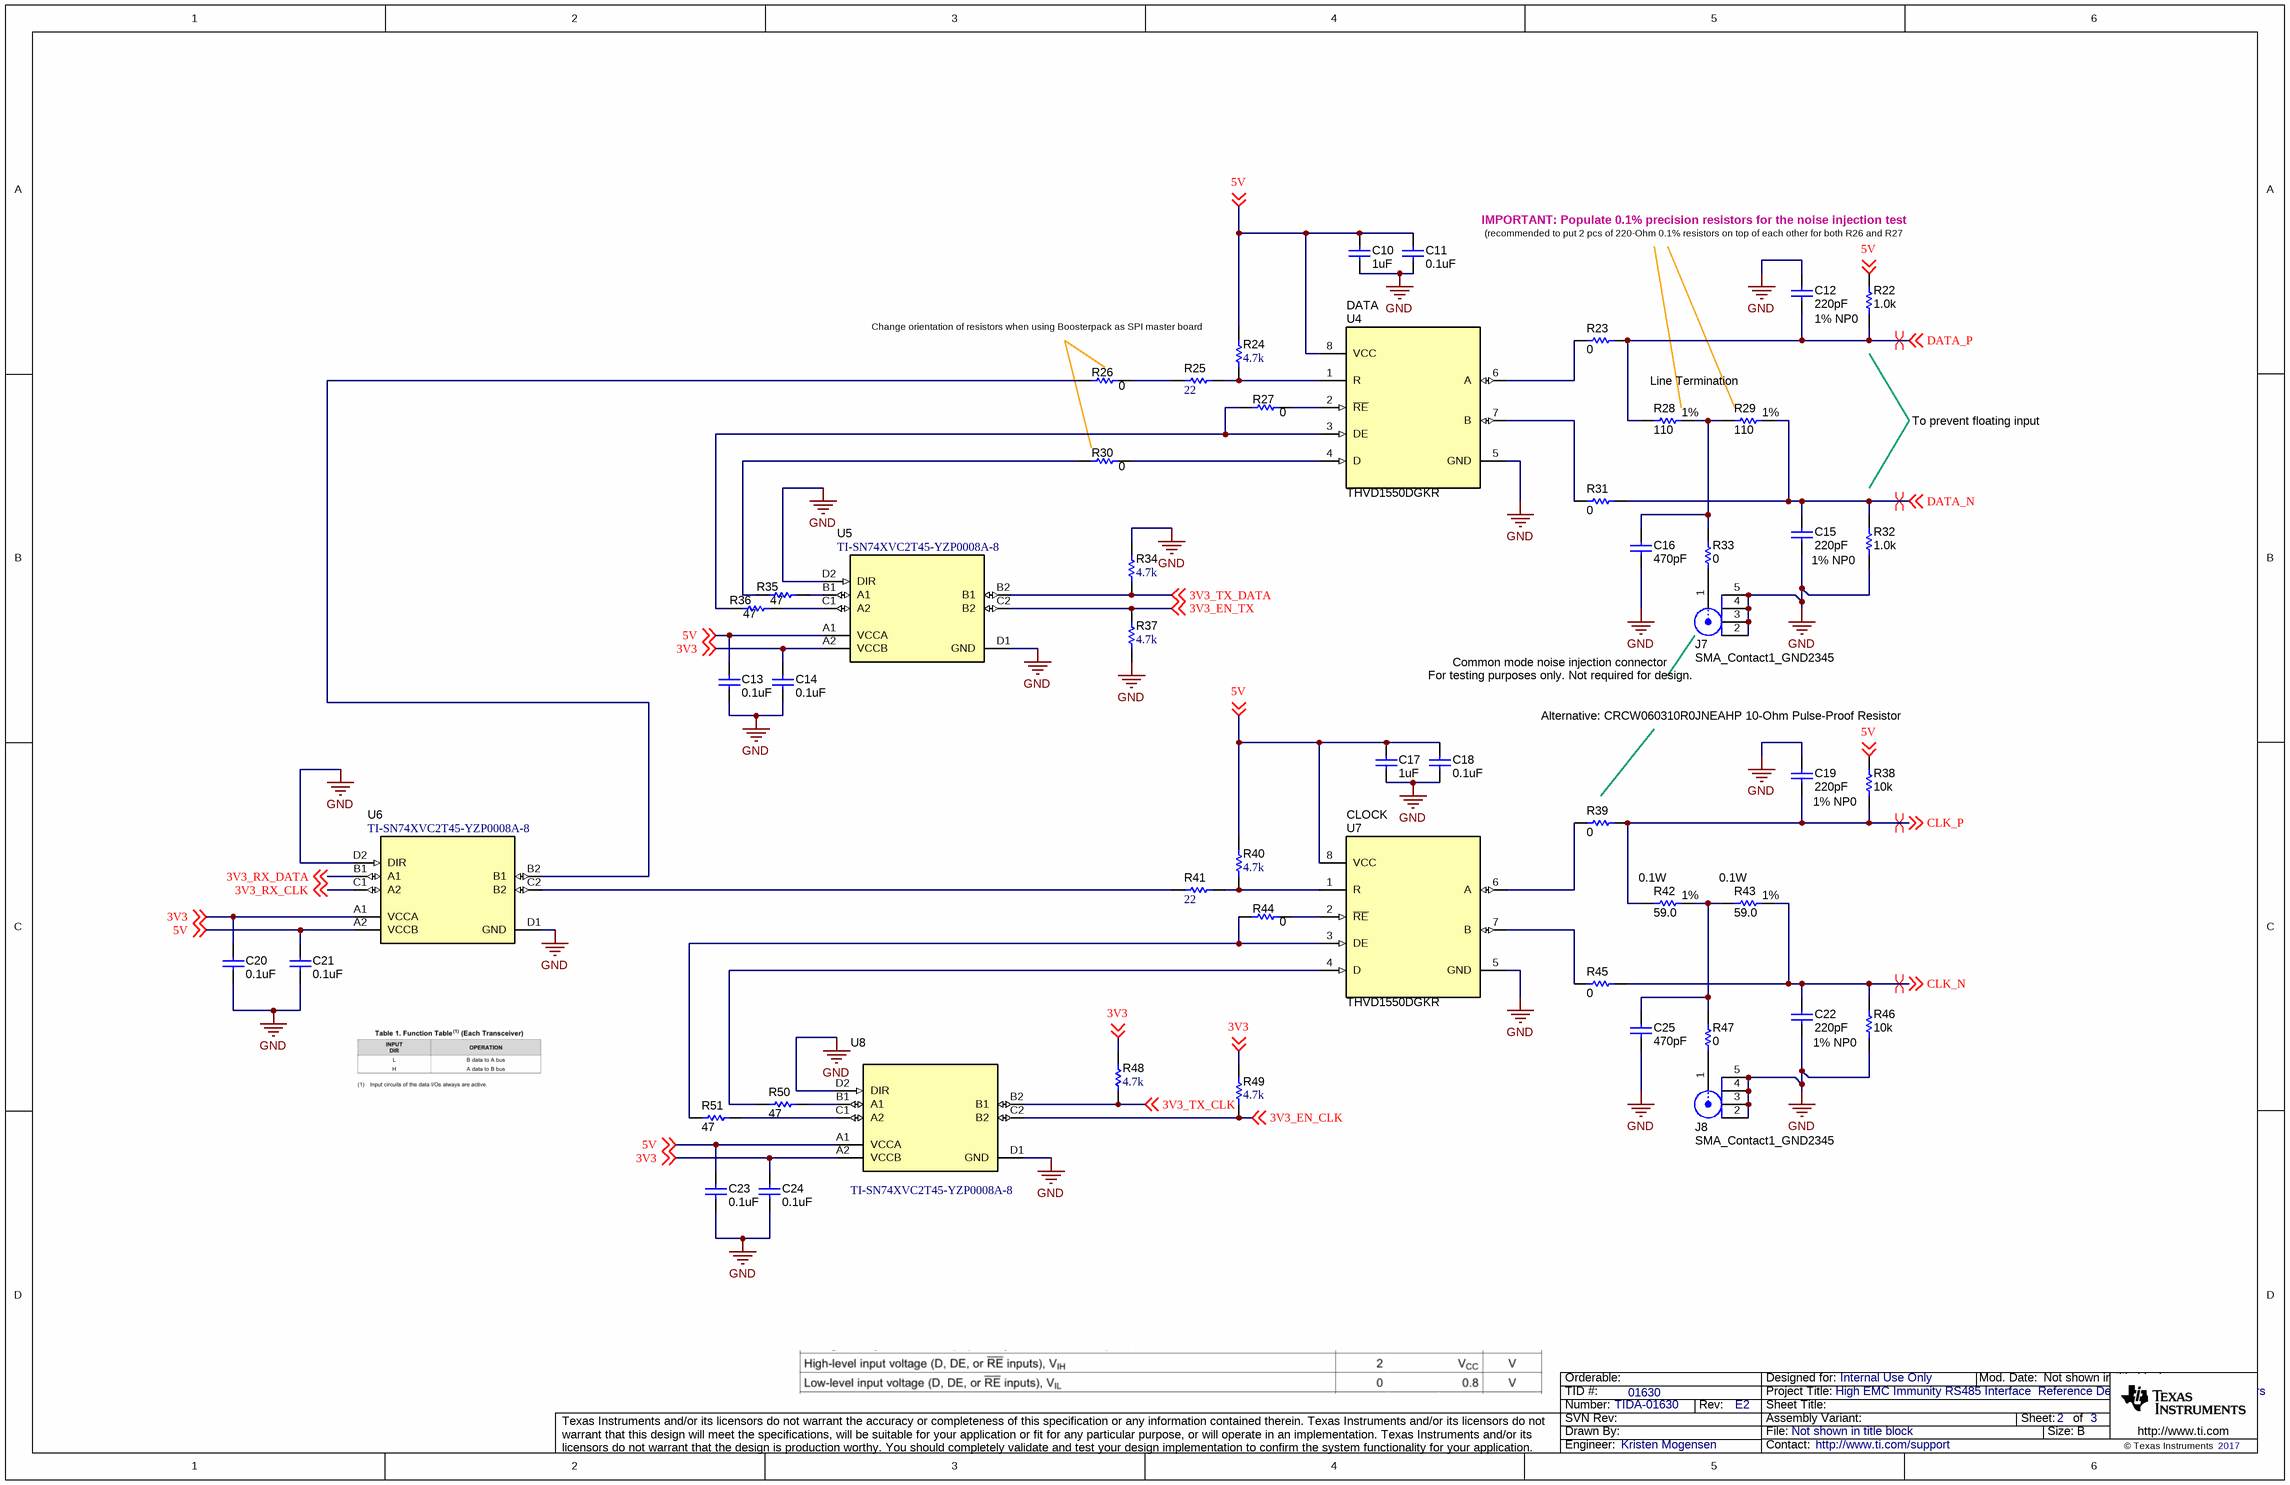
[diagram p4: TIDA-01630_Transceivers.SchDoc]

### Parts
C10  ValueDisplayed: 1uF  [0402S]  (hidden comment: Capacitor)
C11  ValueDisplayed: 0.1uF  [0402S]  (hidden comment: Capacitor)
C12  ValueDisplayed: 220pF  [0603S]  (hidden comment: Capacitor)
C13  ValueDisplayed: 0.1uF  [0402S]  (hidden comment: Capacitor)
C14  ValueDisplayed: 0.1uF  [0402S]  (hidden comment: Capacitor)
C15  ValueDisplayed: 220pF  [0603S]  (hidden comment: Capacitor)
C16  ValueDisplayed: 470pF  [0603S]  (hidden comment: Capacitor)
C17  ValueDisplayed: 1uF  [0402S]  (hidden comment: Capacitor)
C18  ValueDisplayed: 0.1uF  [0402S]  (hidden comment: Capacitor)
C19  ValueDisplayed: 220pF  [0603S]  (hidden comment: Capacitor)
C20  ValueDisplayed: 0.1uF  [0402S]  (hidden comment: Capacitor)
C21  ValueDisplayed: 0.1uF  [0402S]  (hidden comment: Capacitor)
C22  ValueDisplayed: 220pF  [0603S]  (hidden comment: Capacitor)
C23  ValueDisplayed: 0.1uF  [0402S]  (hidden comment: Capacitor)
C24  ValueDisplayed: 0.1uF  [0402S]  (hidden comment: Capacitor)
C25  ValueDisplayed: 470pF  [0603S]  (hidden comment: Capacitor)
J7  SMA_Contact1_GND2345  [Linx_CONSMA001-SMD-G]
J8  SMA_Contact1_GND2345  [Linx_CONSMA001-SMD-G]
R22  ValueDisplayed: 1.0k  [0603S]  (hidden comment: CRCW06031K00JNEA)
R23  ValueDisplayed: 0  [0603S]  (hidden comment: Resistor)
R24  ValueDisplayed: 4.7k  [0402S]  (hidden comment: CRCW04024K70JNED)
R25  ValueDisplayed: 22  [0402S]  (hidden comment: CRCW040222R0JNED)
R26  ValueDisplayed: 0  [0402S]  (hidden comment: Resistor)
R27  ValueDisplayed: 0  [0402S]  (hidden comment: Resistor)
R28  Value1: 1%  ValueDisplayed: 110  [0603S]  (hidden comment: CRCW0603110RFKEA)
R29  Value1: 1%  ValueDisplayed: 110  [0603S]  (hidden comment: CRCW0603110RFKEA)
R30  ValueDisplayed: 0  [0402S]  (hidden comment: Resistor)
R31  ValueDisplayed: 0  [0603S]  (hidden comment: Resistor)
R32  ValueDisplayed: 1.0k  [0603S]  (hidden comment: CRCW06031K00JNEA)
R33  ValueDisplayed: 0  [0402S]  (hidden comment: Resistor)
R34  ValueDisplayed: 4.7k  [0402S]  (hidden comment: CRCW04024K70JNED)
R35  ValueDisplayed: 47  [0402S]  (hidden comment: Resistor)
R36  ValueDisplayed: 47  [0402S]  (hidden comment: Resistor)
R37  ValueDisplayed: 4.7k  [0402S]  (hidden comment: CRCW04024K70JNED)
R38  ValueDisplayed: 10k  [0603S]  (hidden comment: Resistor)
R39  ValueDisplayed: 0  [0603S]  (hidden comment: Resistor)
R40  ValueDisplayed: 4.7k  [0402S]  (hidden comment: CRCW04024K70JNED)
R41  ValueDisplayed: 22  [0402S]  (hidden comment: CRCW040222R0JNED)
R42  ValueDisplayed: 59.0  Value1: 1%  Value2: 0.1W  [0603S]  (hidden comment: Resistor)
R43  ValueDisplayed: 59.0  Value1: 1%  Value2: 0.1W  [0603S]  (hidden comment: Resistor)
R44  ValueDisplayed: 0  [0402S]  (hidden comment: Resistor)
R45  ValueDisplayed: 0  [0603S]  (hidden comment: Resistor)
R46  ValueDisplayed: 10k  [0603S]  (hidden comment: Resistor)
R47  ValueDisplayed: 0  [0402S]  (hidden comment: Resistor)
R48  ValueDisplayed: 4.7k  [0402S]  (hidden comment: CRCW04024K70JNED)
R49  ValueDisplayed: 4.7k  [0402]  (hidden comment: CRCW04024K70JNED)
R50  ValueDisplayed: 47  [0402S]  (hidden comment: Resistor)
R51  ValueDisplayed: 47  [0402S]  (hidden comment: Resistor)
U4  THVD1550DGKR  [DGK0008A_N]
U5  TI-SN74XVC2T45-YZP0008A-8  [YZP0008ADAD]
U6  TI-SN74XVC2T45-YZP0008A-8  [YZP0008ADAD]
U7  THVD1550DGKR  [DGK0008A_N]
U8  TI-SN74XVC2T45-YZP0008A-8  [YZP0008ADAD]

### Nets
GND: C10.2 C11.2 C12.1 C13.1 C14.1 C15.2 C16.2 C17.2 C18.2 C19.1 C20.1 C21.1 C22.2 C23.1 C24.1 C25.2 J7.2 J7.3 J7.4 J7.5 J8.2 J8.3 J8.4 J8.5 R32.1 R34.2 R37.1 R46.1 U4.5(GND) U5.D1(GND) U5.D2(DIR) U6.D1(GND) U6.D2(DIR) U7.5(GND) U8.D1(GND) U8.D2(DIR)
3V3: C14.2 C20.2 C24.2 R48.2 R49.2 U5.A2(VCCB) U6.A1(VCCA) U8.A2(VCCB) ; off-sheet 3V3
3V3_EN_CLK: R49.1 U8.C2(B2) ; off-sheet 3V3_EN_CLK
3V3_EN_TX: R37.2 U5.C2(B2) ; off-sheet 3V3_EN_TX
3V3_RX_CLK: U6.C1(A2) ; off-sheet 3V3_RX_CLK
3V3_RX_DATA: U6.B1(A1) ; off-sheet 3V3_RX_DATA
3V3_TX_CLK: R48.1 U8.B2(B1) ; off-sheet 3V3_TX_CLK
3V3_TX_DATA: R34.1 U5.B2(B1) ; off-sheet 3V3_TX_DATA
5V: C10.1 C11.1 C13.2 C17.1 C18.1 C21.2 C23.2 R22.2 R24.2 R38.2 R40.2 U4.8(VCC) U5.A1(VCCA) U6.A2(VCCB) U7.8(VCC) U8.A1(VCCA) ; off-sheet 5V
CLK_N: C22.1 R43.2 R45.2 R46.2 ; off-sheet CLK_N
CLK_P: C19.2 R38.1 R39.2 R42.1 ; off-sheet CLK_P
DATA_N: C15.1 R29.1 R31.2 R32.2 ; off-sheet DATA_N
DATA_P: C12.2 R22.1 R23.2 R28.2 ; off-sheet DATA_P
NetC16_1: C16.1 R28.1 R29.2 R33.2
NetC25_1: C25.1 R42.2 R43.1 R47.2
NetJ7_1: J7.1 R33.1
NetJ8_1: J8.1 R47.1
NetR23_1: R23.1 U4.6(A)
NetR24_1: R24.1 R25.2 U4.1(R)
NetR25_1: R25.1 R26.2
NetR26_1: R26.1 U6.B2(B1)
NetR27_1: R27.1 R36.1 U4.3(DE)
NetR27_2: R27.2 U4.2(~{RE})
NetR30_1: R30.1 R35.1
NetR30_2: R30.2 U4.4(D)
NetR31_1: R31.1 U4.7(B)
NetR35_2: R35.2 U5.B1(A1)
NetR36_2: R36.2 U5.C1(A2)
NetR39_1: R39.1 U7.6(A)
NetR40_1: R40.1 R41.2 U7.1(R)
NetR41_1: R41.1 U6.C2(B2)
NetR44_1: R44.1 R51.1 U7.3(DE)
NetR44_2: R44.2 U7.2(~{RE})
NetR45_1: R45.1 U7.7(B)
NetR50_1: R50.1 U7.4(D)
NetR50_2: R50.2 U8.B1(A1)
NetR51_2: R51.2 U8.C1(A2)

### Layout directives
differential pair: CLK_N, CLK_P, DATA_N, DATA_P

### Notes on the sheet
- IMPORTANT: Populate 0.1% precision resistors for the noise injection test
- (recommended to put 2 pcs of 220-Ohm 0.1% resistors on top of each other for both R26 and R27
- (near R24) Change orientation of resistors when using Boosterpack as SPI master board
- DATA
- 1% NP0
- Line Termination
- To prevent floating input
- (near J7) Common mode noise injection connector
- (near J7) For testing purposes only. Not required for design.
- Alternative: CRCW060310R0JNEAHP 10-Ohm Pulse-Proof Resistor
- CLOCK

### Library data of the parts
C10 C17 = CMP-0006563-2: CAP, CERM, 1 uF, 10 V, +/- 10%, X5R, 0402; PartNumber: GRM155R61A105KE15D; Manufacturer: MuRata; Polarized: N; Value: 1uF; U/M: EA; Cap_F: 1µF; Value1: Unknown; VDC_V: 10V; TaMin_C: -55°C; TaMax_C: 85°C; Cap_Case: 0402; SizeArea_mm2: 0.5; SizeAreaWB_mm2: 3; SizeX_mm: 1; SizeZ_mm: 0.6; AEC Category: Q200
C11 C13 C14 C18 C20 C21 C23 C24 = CMP-0006228-2: CAP, CERM, 0.1 uF, 16 V, +/- 10%, X7R, 0402; PartNumber: 885012205037; Manufacturer: Wurth Elektronik; Polarized: N; Value: 0.1uF; U/M: EA; Cap_F: 100nF; Value1: Unknown; VDC_V: 16V; TaMin_C: -55°C; TaMax_C: 125°C; Cap_Case: 0402; SizeArea_mm2: 0.5; SizeAreaWB_mm2: 3; SizeX_mm: 1; SizeZ_mm: 0.6; AEC Category: Q200
C12 C15 C19 C22 = CMP-0006776-4: CAP, CERM, 220 pF, 50 V, +/- 1%, C0G/NP0, 0603; PartNumber: 06035A221FAT2A; Manufacturer: AVX; Polarized: N; Value: 220pF; U/M: EA; ESR_ohm: 0.083; Value1: 0.083 ohm; VDC_V: 50V; TaMin_C: -55°C; TaMax_C: 125°C; Cap_Case: 0603; SizeArea_mm2: 1.28; SizeAreaWB_mm2: 4.68; SizeX_mm: 1.6; SizeY_mm: 0.8; SizeZ_mm: 1; AEC Category: Q200
C16 C25 = CMP-0006834-5: CAP, CERM, 470 pF, 50 V, +/- 10%, X7R, 0603; PartNumber: 885012206081; Manufacturer: Wurth Elektronik; Polarized: N; Value: 470pF; U/M: EA; Value1: Unknown; VDC_V: 50V; TaMin_C: -55°C; TaMax_C: 125°C; Cap_Case: 0603; SizeArea_mm2: 1.28; SizeAreaWB_mm2: 4.68; SizeX_mm: 1.6; SizeY_mm: 0.8; SizeZ_mm: 1; AEC Category: Q200
J7 J8 = CMP-0055834-1: Jack, SMA, PCB, Gold, SMT; PartNumber: CONSMA001-SMD-G; Manufacturer: Linx Technologies; CNHeader: FALSE; CT: TRUE
R22 R32 = CMP-0025729-4: RES, 1.0 k, 5%, 0.1 W, AEC-Q200 Grade 0, 0603; Manufacturer: Vishay-Dale; Power_W: 100mW; TempCo: 200 ppm/C; Value_Code: 1k00; Value: 1.0k; EIA_Code: E24; Res_ohm: 1k; SizeX_mm: 1.6; SizeY_mm: 0.8; SizeZ_mm: 1; Value2: 0.1W; SizeArea_mm2: 1.28; CompType: Resistor; AEC Qualified: Y; VDC_V: 75V; AEC Category: Q200; AEC Grade: 0
R23 R31 R39 R45 = CMP-0025697-4: RES, 0, 5%, 0.1 W, AEC-Q200 Grade 0, 0603; PartNumber: CRCW06030000Z0EA; Manufacturer: Vishay-Dale; Value: 0; Value_Code: 0000; Power_W: 100mW; Value2: 0.1W; VDC_V: 75V; TempCo: 200 ppm/C; EIA_Code: E24; SizeArea_mm2: 1.28; SizeX_mm: 1.6; SizeY_mm: 0.8; SizeZ_mm: 1; AEC Category: Q200; AEC Qualified: Y
R24 R34 R37 R40 R48 R49 = CMP-0026938-4: RES, 4.7 k, 5%, 0.063 W, 0402; Manufacturer: Vishay-Dale; Power_W: 63mW; TempCo: 200 ppm/C; Value_Code: 4k70; U/M: EA; Value: 4.7k; EIA_Code: E24; SizeX_mm: 1; SizeY_mm: 0.5; SizeZ_mm: 0.6; Value2: 0.063W; CompType: Resistor; VDC_V: 50V; AEC Category: Q200
R25 R41 = CMP-0026880-2: as R6 on sheet TIDA-01630_Interface
R26 R27 R30 R33 R44 R47 = CMP-0026822-3: as R4 on sheet TIDA-01630_Interface
R28 R29 = CMP-0022009-5: RES, 110, 1%, 0.1 W, AEC-Q200 Grade 0, 0603; Manufacturer: Vishay-Dale; Power_W: 100mW; TempCo: 100 ppm/C; Value_Code: 110R; Value: 110; EIA_Code: E96; SizeX_mm: 1.6; SizeY_mm: 0.8; SizeZ_mm: 1; Value2: 0.1W; SizeArea_mm2: 1.28; CompType: Resistor; AEC Qualified: Y; VDC_V: 75V; AEC Category: Q200; AEC Grade: 0
R35 R36 R50 R51 = CMP-0026936-3: RES, 47, 5%, 0.063 W, AEC-Q200 Grade 0, 0402; PartNumber: CRCW040247R0JNED; Manufacturer: Vishay-Dale; Value: 47; Value_Code: 47R0; Power_W: 63mW; Value2: 0.063W; VDC_V: 50V; TempCo: 200 ppm/C; SizeArea_mm2: 0.5; SizeX_mm: 1; SizeZ_mm: 0.6; EIA_Code: E24; AEC Category: Q200; AEC Qualified: Y; AEC Grade: 0
R38 R46 = CMP-0025701-4: RES, 10 k, 5%, 0.1 W, AEC-Q200 Grade 0, 0603; PartNumber: CRCW060310K0JNEA; Manufacturer: Vishay-Dale; Value: 10k; Value_Code: 10k0; Power_W: 100mW; Value2: 0.1W; VDC_V: 75V; TempCo: 200 ppm/C; SizeArea_mm2: 1.28; SizeX_mm: 1.6; SizeY_mm: 0.8; SizeZ_mm: 1; EIA_Code: E24; AEC Category: Q200; AEC Qualified: Y; AEC Grade: 0
R42 R43 = CMP-0023196-3: RES, 59.0, 1%, 0.1 W, 0603; PartNumber: RC0603FR-0759RL; Manufacturer: Yageo America; Value: 59.0; Res_ohm: 59; Value_Code: 59R0; Power_W: 100mW; VDC_V: 150V; TempCo: 200 ppm/C; SizeArea_mm2: 1.28; SizeX_mm: 1.6; SizeY_mm: 0.8; SizeZ_mm: 1; EIA_Code: E96; U/M: EA; AEC Category: Q200
U4 U7 = CMP-0074780-2: 5-V RS-485 Transceivers With +/-16-kV IEC ESD Protection, DGK0008A (VSSOP-8); Manufacturer: Texas Instruments; SizeX_mm: 5.05; SizeY_mm: 3.1; CompType: IC; SizeZ_mm: 1.1; SizeArea_mm2: 15.655; SizeAreaWB_mm2: 35.955; U/M: EA
U5 U6 U8 = CMP-0051062-2: Dual-Bit Dual Supply Transceiver with Configurable Voltage Translation and 3-State Outputs, YZP0008ADAD, LARGE T&R; PartNumber: SN74LVC2T45YZPR; Manufacturer: Texas Instruments; Generic Part Number: SN74LVC2T45; 3-State Output: Yes; Bits(#): 2; F @ Nom Voltage(Max)(Mhz): 150; ICC @ Nom Voltage(Max)(mA): 0.004; Input Type: CMOS/TTL; Logic: True; Output Drive (IOL/IOH)(Max)(mA): 32/-32; Output Type: CMOS; Rating: Military; Schmitt Trigger: No; Sub-Family: Dual Supply Translator; Technology Family: LVC; tpd @ Nom Voltage(Max)(ns): 17.7,10.3,8.3,7.2; VCC(Max)(V): 5.5; VCC(Min)(V): 1.65; Voltage(Nom)(V): 1.8,2.5,3.3,5

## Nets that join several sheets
GND: TIDA-01630_Interface (19 pins), TIDA-01630_PowerSupply (18 pins), TIDA-01630_Transceivers (36 pins)
3V3: TIDA-01630_Interface (R2.1), TIDA-01630_PowerSupply (10 pins), TIDA-01630_Transceivers (8 pins)
3V3_EN_CLK: TIDA-01630_Interface (J3.17), TIDA-01630_Transceivers (R49.1 U8.C2)
3V3_EN_TX: TIDA-01630_Interface (J4.7), TIDA-01630_Transceivers (R37.2 U5.C2)
3V3_ENABLE_5V: TIDA-01630_Interface (J4.20), TIDA-01630_PowerSupply (R19.1 R21.2 U2.C1)
3V3_ENC_PWR_EN: TIDA-01630_Interface (J4.18), TIDA-01630_PowerSupply (R13.1)
3V3_RX_CLK: TIDA-01630_Interface (R7.1), TIDA-01630_Transceivers (U6.C1)
3V3_RX_DATA: TIDA-01630_Interface (J4.12), TIDA-01630_Transceivers (U6.B1)
3V3_TX_CLK: TIDA-01630_Interface (J1.3 J4.1), TIDA-01630_Transceivers (R48.1 U8.B2)
3V3_TX_DATA: TIDA-01630_Interface (R6.2), TIDA-01630_Transceivers (R34.1 U5.B2)
5V: TIDA-01630_PowerSupply (C9.1 R18.2), TIDA-01630_Transceivers (16 pins)
CLK_N: TIDA-01630_Interface (D1.1 J6.7 R4.2), TIDA-01630_Transceivers (C22.1 R43.2 R45.2 R46.2)
CLK_P: TIDA-01630_Interface (D1.2 J6.8 R5.1), TIDA-01630_Transceivers (C19.2 R38.1 R39.2 R42.1)
DATA_N: TIDA-01630_Interface (D2.1 J2.13 J6.4), TIDA-01630_Transceivers (C15.1 R29.1 R31.2 R32.2)
DATA_P: TIDA-01630_Interface (D2.2 J2.5 J6.5), TIDA-01630_Transceivers (C12.2 R22.1 R23.2 R28.2)
VIN: TIDA-01630_Interface (D6.1 J5.1), TIDA-01630_PowerSupply (5 pins)
Vsupply_Enc: TIDA-01630_Interface (J2.4 J6.2), TIDA-01630_PowerSupply (C3.1 R14.2 R15.1 U1.6)

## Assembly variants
001: not fitted C1 C1 C10 C13 C14 C16 C17 C18 C22 C23 C23 C24 C25 D1 D2 J9 J10 R1 R5 R8 R18 R23 R23 R33 R36 R38 R39 R40 R41 R42 R43 R44 R45 R45 R46 R48 R49 R50 R51 TP1 TP2 TP3 U7 U8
